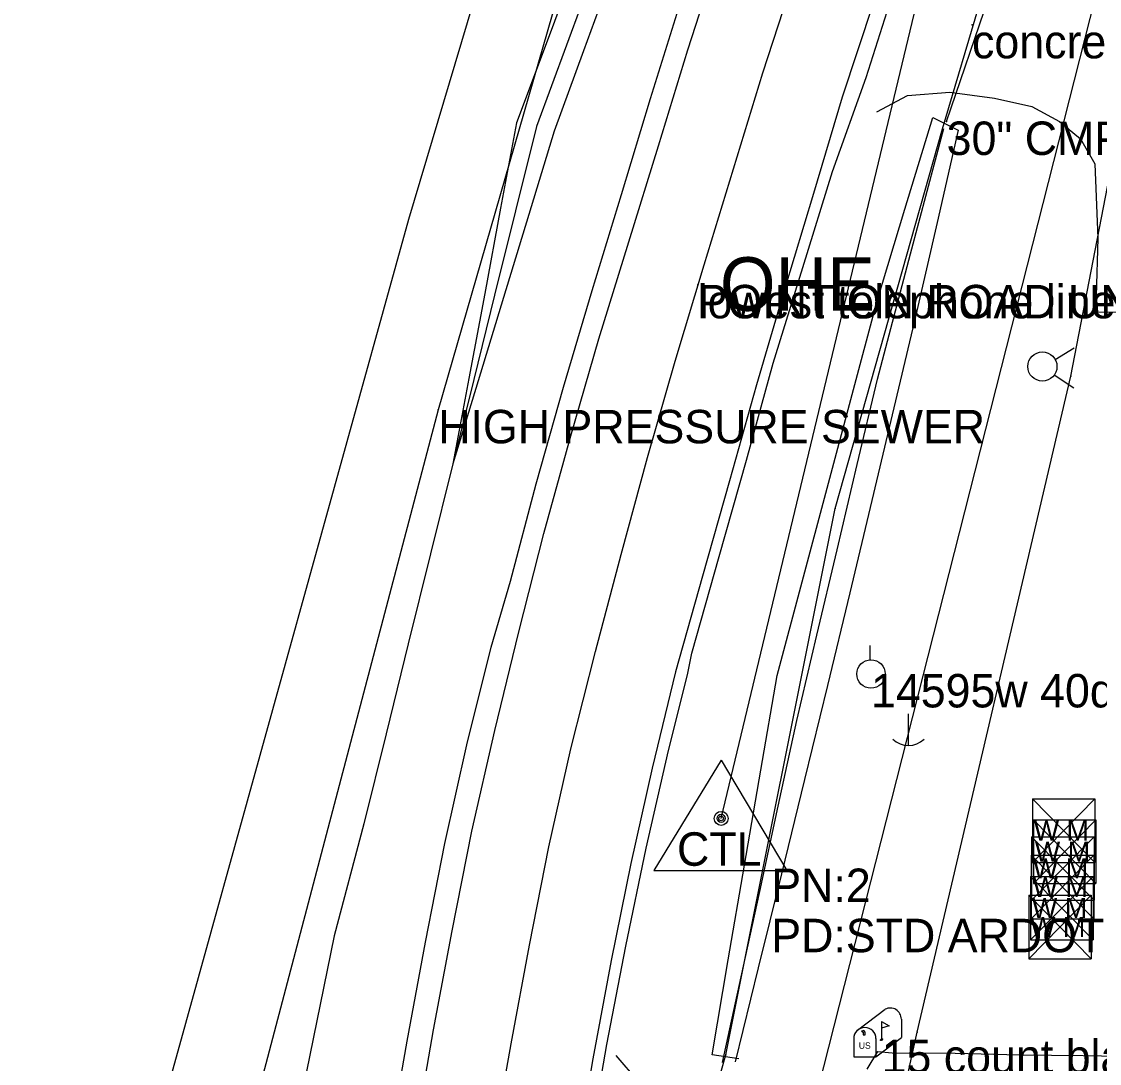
# Model space of a CAD drawing. Extents: x 1802180 to 1804859, y 572524 to 575172.
# Drawn here: x 1803144.4 to 1803305.5, y 573011.4 to 573167.1 of the extents above; entities that cross this region are included whole.
import ezdxf

# ---------------------------------------------------------------- set-up
doc = ezdxf.new("R2010")
doc.units = 0
for name, color, linetype in [('EX_EDGE_PAVEMENT', 7, 'Continuous'), ('EX_SHOULDER', 7, 'Continuous'), ('S_BASELINE', 7, 'Continuous'), ('S_DITCHLINE', 7, 'Continuous'), ('S_DRG_PT_SYM', 7, 'Continuous'), ('S_ELECTRIC_UTILITIES_ANNOT', 7, 'Continuous'), ('S_GAS_UTILITIES', 7, 'Continuous'), ('S_MAILBOX', 7, 'Continuous'), ('S_MAILBOX_ANNOT', 7, 'Continuous'), ('S_MISC_BOUNDARY', 7, 'Continuous'), ('S_MSC_PT_SYM', 7, 'Continuous'), ('S_PARKING', 7, 'Continuous'), ('S_PAVEMENT_CROWN', 7, 'Continuous'), ('S_PRIMARY_CTL', 7, 'Continuous'), ('S_PRIMARY_CTL_ANNOT', 7, 'Continuous'), ('S_SANITARY_SEWER', 7, 'Continuous'), ('S_SANITARY_SEWER_ANNOT', 7, 'Continuous'), ('S_SHOULDER', 7, 'Continuous'), ('S_SIDE_DRAIN', 7, 'Continuous'), ('S_SIDE_DRAIN_ANNOT', 7, 'Continuous'), ('S_SURVEY_TEXT', 7, 'Continuous'), ('S_SURVEY_TEXT_ANNOT', 7, 'Continuous'), ('S_UTILITY_POLE', 7, 'Continuous'), ('S_UTILITY_POLE_ANNOT', 7, 'Continuous'), ('S_UTL_PT_SYM', 7, 'Continuous'), ('S_WATER_UTILITIES', 7, 'Continuous')]:
    doc.layers.add(name, color=color, linetype=linetype)

msp = doc.modelspace()

# ---------------------------------------------------------------- linework, layer by layer
at = {"layer": 'EX_EDGE_PAVEMENT'}
for points in [[(1803203.33, 573001.42), (1803205.96, 573016.44), (1803208.73, 573031.24), (1803211.69, 573046.13), (1803215.08, 573061.15), (1803218.68, 573075.89), (1803222.45, 573090.57), (1803226.48, 573105.2), (1803230.65, 573119.7), (1803235.11, 573134.16), (1803239.56, 573148.5), (1803243.97, 573162.84), (1803248.63, 573177.34)], [(1803271.65, 573169.78), (1803267.02, 573155.77), (1803262.74, 573141.39), (1803258.4, 573127.05), (1803254.23, 573112.79), (1803250.16, 573098.45), (1803246.13, 573084.2), (1803242.13, 573069.91), (1803238.63, 573055.52), (1803235.44, 573041.29), (1803232.5, 573026.78), (1803229.77, 573012.09), (1803227.31, 572997.57)]]:
    msp.add_lwpolyline(points, dxfattribs=at)
at = {"layer": 'EX_SHOULDER'}
for points in [[(1803244.54, 573072.71), (1803248.63, 573087.13), (1803252.74, 573101.56), (1803256.68, 573116.02), (1803261.13, 573130.33), (1803265.55, 573144.67), (1803270.59, 573158.74), (1803275.14, 573173.03), (1803279.82, 573187.3), (1803284.37, 573201.59), (1803289.02, 573215.83), (1803293.78, 573230.06), (1803298.55, 573244.28), (1803303.32, 573258.5), (1803308.12, 573272.7), (1803312.96, 573286.9), (1803317.8, 573301.09), (1803322.64, 573315.29), (1803327.4, 573329.51), (1803332.12, 573343.77), (1803336.9, 573357.97)], [(1803217.45, 573083.45), (1803221.29, 573098), (1803225.36, 573112.47), (1803229.64, 573126.91), (1803234.04, 573141.25), (1803238.37, 573155.6), (1803242.85, 573169.96), (1803247.56, 573184.22), (1803252.29, 573198.46), (1803256.96, 573212.72), (1803261.68, 573226.97), (1803266.49, 573241.18), (1803271.3, 573255.39), (1803276.08, 573269.61), (1803280.88, 573283.83), (1803285.7, 573298.03), (1803290.52, 573312.24), (1803295.34, 573326.45), (1803300.24, 573340.63), (1803305.01, 573354.83)]]:
    msp.add_lwpolyline(points, dxfattribs=at)
at = {"layer": 'S_BASELINE'}
msp.add_line((1803248.92, 573048.02), (1803445.92, 573868.28), dxfattribs=at)
at = {"layer": 'S_DITCHLINE'}
for points in [[(1803289.39, 573359.67), (1803285.18, 573345.84), (1803280.96, 573332.01), (1803276.75, 573318.18), (1803272.53, 573304.35), (1803268.08, 573291.91), (1803263.63, 573279.47), (1803259.18, 573267.02), (1803254.72, 573254.58), (1803250.18, 573241.12), (1803245.65, 573227.66), (1803241.11, 573214.21), (1803236.57, 573200.75), (1803232.01, 573188.55), (1803227.46, 573176.35), (1803222.91, 573164.14), (1803218.36, 573151.94), (1803215.97, 573139.2), (1803213.59, 573126.47), (1803211.2, 573113.73), (1803208.82, 573100.99)], [(1803294.83, 573357.82), (1803290.52, 573344.09), (1803286.21, 573330.36), (1803281.9, 573316.63), (1803277.59, 573302.9), (1803273.2, 573290.32), (1803268.8, 573277.73), (1803264.41, 573265.15), (1803260.01, 573252.56), (1803255.39, 573239.11), (1803250.78, 573225.66), (1803246.16, 573212.21), (1803241.54, 573198.76), (1803237.14, 573186.74), (1803232.74, 573174.73), (1803228.35, 573162.72), (1803223.95, 573150.71), (1803220.17, 573138.28), (1803216.38, 573125.85), (1803212.6, 573113.42), (1803208.82, 573100.99)], [(1803230.29, 573175.75), (1803225.81, 573163.57), (1803221.33, 573151.39), (1803218.2, 573138.79), (1803215.07, 573126.19), (1803211.94, 573113.59), (1803208.82, 573100.99), (1803205.49, 573087.55), (1803202.16, 573074.11), (1803198.84, 573060.67), (1803195.51, 573047.23), (1803191.07, 573030.48), (1803186.39, 573007.51)], [(1803251.58, 573012.08), (1803247.57, 573012.69), (1803250, 573026.87), (1803252.44, 573041.04), (1803254.87, 573055.21), (1803257.31, 573069.39), (1803261.04, 573083.38), (1803264.77, 573097.38), (1803268.51, 573111.37), (1803272.24, 573125.36), (1803276.4, 573139.05), (1803280.56, 573152.73), (1803284.37, 573150.88), (1803281.21, 573137.04), (1803278.04, 573123.2), (1803274.74, 573109.37), (1803271.44, 573095.54), (1803268.14, 573081.71), (1803264.84, 573067.88), (1803261.39, 573053.82), (1803257.94, 573039.76), (1803254.48, 573025.7), (1803251.03, 573011.63)], [(1803249.15, 573011.56), (1803251.92, 573024.33), (1803254.69, 573037.09), (1803257.46, 573049.86), (1803260.23, 573062.63), (1803263.25, 573075.38), (1803266.26, 573088.13), (1803269.28, 573100.88), (1803272.29, 573113.64), (1803277.25, 573132.37), (1803282.21, 573151.11)]]:
    msp.add_lwpolyline(points, dxfattribs=at)
at = {"layer": 'S_DRG_PT_SYM'}
msp.add_lwpolyline([(1803282.63, 573152.15), (1803282.63, 573152.2), (1803282.63, 573152.15), (1803282.58, 573152.15), (1803282.63, 573152.15), (1803282.63, 573152.1), (1803282.63, 573152.15), (1803282.68, 573152.15)], dxfattribs=at)
at = {"layer": 'S_GAS_UTILITIES'}
for p, q in [((1803282.01, 573151.05), (1803291.88, 573184.33)), ((1803265.95, 573094.32), (1803282.01, 573151.05)), ((1803249.61, 573012.7), (1803265.95, 573094.32)), ((1803239.64, 572977.11), (1803249.61, 573012.7))]:
    msp.add_line(p, q, dxfattribs=at)
at = {"layer": 'S_MAILBOX'}
for p, q in [((1803269.29, 573016.38), (1803273.43, 573019.49)), ((1803272.91, 573017.67), (1803272.91, 573014.96)), ((1803275.86, 573018.02), (1803275.86, 573015.3)), ((1803272.06, 573012.39), (1803275.86, 573015.3)), ((1803268.74, 573015.11), (1803268.74, 573012.39)), ((1803272.06, 573015.11), (1803272.06, 573012.39)), ((1803268.74, 573012.39), (1803272.06, 573012.39))]:
    msp.add_line(p, q, dxfattribs=at)
for points in [[(1803272.91, 573017.67), (1803274.02, 573017.01), (1803272.91, 573016.66)], [(1803269.92, 573016.22), (1803270.15, 573016.09), (1803270.15, 573015.7), (1803270.45, 573015.7), (1803270.45, 573016.06), (1803270.26, 573016.31), (1803269.92, 573016.25)]]:
    msp.add_lwpolyline(points, dxfattribs=at)
for centre, end in [((1803274.2, 573018.02), 117.5718), ((1803270.4, 573015.11), 180)]:
    msp.add_arc(centre, 1.66, 0, end, dxfattribs=at)
msp.add_ellipse((1803272.91, 573014.96), major_axis=(0.145, 0.132), ratio=0.564646, dxfattribs=at)
at = {"layer": 'S_MISC_BOUNDARY'}
msp.add_lwpolyline([(1802880.88, 573735.6), (1803051.71, 573733.48), (1803213.27, 573730.83), (1803216.46, 573532.09), (1803301.63, 573530.07), (1803296.75, 573432.28), (1803274.96, 573355.36), (1803226.68, 573219.53), (1803202.19, 573137.5), (1803157.77, 572977.33), (1803158.5, 572726.69), (1802889.88, 572728.1)], dxfattribs=at)
at = {"layer": 'S_MSC_PT_SYM'}
for points in [[(1803286.42, 573166.59), (1803286.42, 573166.64), (1803286.42, 573166.59), (1803286.37, 573166.59), (1803286.42, 573166.59), (1803286.42, 573166.54), (1803286.42, 573166.59), (1803286.47, 573166.59)], [(1803245.42, 573127.74), (1803245.42, 573127.79), (1803245.42, 573127.74), (1803245.37, 573127.74), (1803245.42, 573127.74), (1803245.42, 573127.69), (1803245.42, 573127.74), (1803245.47, 573127.74)]]:
    msp.add_lwpolyline(points, dxfattribs=at)
at = {"layer": 'S_PARKING'}
for points in [[(1803272.22, 573153.62), (1803276.76, 573156.03), (1803283.12, 573156.53), (1803289.76, 573155.63), (1803295.36, 573154.41), (1803299.49, 573152.13), (1803302.62, 573149.58), (1803304.78, 573145.84), (1803305.21, 573134.7), (1803304.96, 573126.07), (1803305.2, 573123.69), (1803309.92, 573123.68), (1803319.81, 573123.41), (1803331.78, 573123.25), (1803335.8, 573123.23), (1803335.81, 573122.76), (1803335.65, 573117.44), (1803339.14, 573117.28)], [(1803272.22, 573153.62), (1803276.76, 573156.03), (1803283.12, 573156.53), (1803289.76, 573155.63), (1803295.36, 573154.41), (1803299.49, 573152.13), (1803302.62, 573149.58), (1803304.78, 573145.84), (1803305.21, 573134.7), (1803304.96, 573126.07), (1803305.2, 573123.69), (1803309.92, 573123.68)], [(1803233.2, 573012.6), (1803236.54, 573008.71)], [(1803233.2, 573012.6), (1803236.54, 573008.71)], [(1803270.73, 573010.53), (1803272.33, 573013.18), (1803274.47, 573013.01), (1803283.9, 573012.93), (1803293.57, 573012.71), (1803303.01, 573012.57), (1803308.51, 573012.47), (1803323.55, 573012.32), (1803327.49, 573012.2), (1803342.61, 573012.05), (1803352.87, 573011.83), (1803367.72, 573011.79), (1803375.31, 573011.48), (1803390.31, 573011.23)], [(1803270.73, 573010.53), (1803272.33, 573013.18), (1803274.47, 573013.01), (1803283.9, 573012.93), (1803293.57, 573012.71), (1803303.01, 573012.57), (1803308.51, 573012.47), (1803323.55, 573012.32), (1803327.49, 573012.2), (1803342.61, 573012.05), (1803352.87, 573011.83), (1803367.72, 573011.79), (1803375.31, 573011.48), (1803390.31, 573011.23)]]:
    msp.add_lwpolyline(points, dxfattribs=at)
at = {"layer": 'S_PAVEMENT_CROWN'}
msp.add_lwpolyline([(1803214.89, 572999.56), (1803217.53, 573014.33), (1803220.29, 573029.07), (1803223.17, 573043.79), (1803226.47, 573058.42), (1803230.13, 573072.97), (1803233.98, 573087.47), (1803237.94, 573101.93), (1803242.08, 573116.35), (1803246.37, 573130.72), (1803250.76, 573145.07), (1803255.16, 573159.41), (1803259.77, 573173.68)], dxfattribs=at)
at = {"layer": 'S_PRIMARY_CTL'}
for p, q in [((1803248.92, 573056.72), (1803238.89, 573040.21)), ((1803248.92, 573056.72), (1803258.74, 573040.21)), ((1803238.89, 573040.21), (1803258.74, 573040.21))]:
    msp.add_line(p, q, dxfattribs=at)
for radius in [1.04, 0.609, 0.344]:
    msp.add_circle((1803248.92, 573048.02), radius, dxfattribs=at)
at = {"layer": 'S_SANITARY_SEWER'}
for p, q in [((1803235.59, 573209.54), (1803206.64, 573109.06)), ((1803253.84, 572969.86), (1803305.33, 573172.39)), ((1803206.64, 573109.06), (1803178.99, 573004.24))]:
    msp.add_line(p, q, dxfattribs=at)
at = {"layer": 'S_SHOULDER'}
for points in [[(1803188.06, 572774.94), (1803187.64, 572789.93), (1803187.25, 572804.96), (1803187.05, 572819.98), (1803186.96, 572835.01), (1803187.13, 572850.03), (1803187.6, 572865.07), (1803188.05, 572880.08), (1803188.63, 572895.09), (1803189.46, 572910.14), (1803190.47, 572925.15), (1803191.68, 572940.15), (1803193.18, 572955.14), (1803195.08, 572970.09), (1803197.21, 572985), (1803199.42, 572999.92), (1803202, 573014.73), (1803204.73, 573029.52), (1803207.64, 573044.28), (1803210.93, 573059.01), (1803214.56, 573073.63), (1803217.45, 573083.45)], [(1803217.19, 572775.54), (1803216.95, 572790.56), (1803216.67, 572805.5), (1803216.65, 572820.48), (1803216.72, 572835.48), (1803217.08, 572850.44), (1803217.44, 572865.41), (1803217.82, 572880.43), (1803218.13, 572895.35), (1803219.14, 572910.28), (1803220.26, 572925.21), (1803221.76, 572940.08), (1803223.21, 572954.99), (1803224.98, 572969.82), (1803227.01, 572984.65), (1803229.31, 572999.47), (1803231.85, 573014.23), (1803234.7, 573028.93), (1803237.73, 573043.58), (1803241.04, 573058.18), (1803243.89, 573069.48), (1803244.54, 573072.71)]]:
    msp.add_lwpolyline(points, dxfattribs=at)
at = {"layer": 'S_SIDE_DRAIN'}
msp.add_line((1803282.63, 573152.15), (1803292.48, 573181.22), dxfattribs=at)
at = {"layer": 'S_SURVEY_TEXT'}
msp.add_line((1803248.74, 573123.87), (1803248.74, 573123.87), dxfattribs=at)
at = {"layer": 'S_UTILITY_POLE'}
for p, q in [((1803271.2, 573071.74), (1803271.2, 573073.85)), ((1803276.86, 573063.63), (1803276.86, 573058.9))]:
    msp.add_line(p, q, dxfattribs=at)
msp.add_circle((1803271.32, 573069.6), 2.13, dxfattribs=at)
msp.add_arc((1803276.92, 573062.33), 3.41, 226.3972, 313.6028, dxfattribs=at)
at = {"layer": 'S_UTL_PT_SYM'}
for points in [[(1803282.01, 573151.05), (1803282.01, 573151.1), (1803282.01, 573151.05), (1803281.96, 573151.05), (1803282.01, 573151.05), (1803282.01, 573151), (1803282.01, 573151.05), (1803282.06, 573151.05)], [(1803245.42, 573127.74), (1803245.42, 573127.79), (1803245.42, 573127.74), (1803245.37, 573127.74), (1803245.42, 573127.74), (1803245.42, 573127.69), (1803245.42, 573127.74), (1803245.47, 573127.74)], [(1803301.21, 573114.11), (1803301.21, 573114.16), (1803301.21, 573114.11), (1803301.16, 573114.11), (1803301.21, 573114.11), (1803301.21, 573114.06), (1803301.21, 573114.11), (1803301.26, 573114.11)], [(1803206.64, 573109.06), (1803206.64, 573109.11), (1803206.64, 573109.06), (1803206.59, 573109.06), (1803206.64, 573109.06), (1803206.64, 573109.01), (1803206.64, 573109.06), (1803206.69, 573109.06)], [(1803265.95, 573094.32), (1803265.95, 573094.37), (1803265.95, 573094.32), (1803265.9, 573094.32), (1803265.95, 573094.32), (1803265.95, 573094.27), (1803265.95, 573094.32), (1803266, 573094.32)], [(1803278.2, 573016.08), (1803278.2, 573016.13), (1803278.2, 573016.08), (1803278.15, 573016.08), (1803278.2, 573016.08), (1803278.2, 573016.03), (1803278.2, 573016.08), (1803278.25, 573016.08)], [(1803249.61, 573012.7), (1803249.61, 573012.75), (1803249.61, 573012.7), (1803249.56, 573012.7), (1803249.61, 573012.7), (1803249.61, 573012.65), (1803249.61, 573012.7), (1803249.66, 573012.7)]]:
    msp.add_lwpolyline(points, dxfattribs=at)
at = {"layer": 'S_WATER_UTILITIES'}
for p, q in [((1803301.21, 573114.11), (1803313.18, 573176.27)), ((1803298.85, 573116.6), (1803301.67, 573118.33)), ((1803278.2, 573016.08), (1803301.21, 573114.11)), ((1803298.72, 573114.29), (1803301.63, 573112.36)), ((1803295.45, 573050.93), (1803304.79, 573050.93)), ((1803295.45, 573050.93), (1803295.45, 573041.44)), ((1803295.45, 573050.93), (1803304.79, 573041.44)), ((1803304.79, 573050.93), (1803295.45, 573041.44)), ((1803304.79, 573050.93), (1803304.79, 573041.44)), ((1803295.61, 573047.79), (1803304.95, 573047.79)), ((1803295.61, 573047.79), (1803295.61, 573038.29)), ((1803295.61, 573047.79), (1803304.95, 573038.29)), ((1803304.95, 573047.79), (1803295.61, 573038.29)), ((1803304.95, 573047.79), (1803304.95, 573038.29)), ((1803295.32, 573045.28), (1803304.66, 573045.28)), ((1803295.32, 573045.28), (1803295.32, 573035.78)), ((1803295.32, 573045.28), (1803304.66, 573035.78)), ((1803304.66, 573045.28), (1803295.32, 573035.78)), ((1803304.66, 573045.28), (1803304.66, 573035.78)), ((1803295.27, 573042.51), (1803304.61, 573042.51)), ((1803295.27, 573042.51), (1803295.27, 573033.02)), ((1803295.27, 573042.51), (1803304.61, 573033.02)), ((1803304.61, 573042.51), (1803295.27, 573033.02)), ((1803295.45, 573041.44), (1803304.79, 573041.44)), ((1803304.61, 573042.51), (1803304.61, 573033.02)), ((1803295.17, 573039.36), (1803304.51, 573039.36)), ((1803295.17, 573039.36), (1803295.17, 573029.86)), ((1803295.17, 573039.36), (1803304.51, 573029.86)), ((1803304.51, 573039.36), (1803295.17, 573029.86)), ((1803295.61, 573038.29), (1803304.95, 573038.29)), ((1803304.51, 573039.36), (1803304.51, 573029.86)), ((1803294.9, 573036.53), (1803304.24, 573036.53)), ((1803294.9, 573036.53), (1803294.9, 573027.04)), ((1803294.9, 573036.53), (1803304.24, 573027.04)), ((1803304.24, 573036.53), (1803294.9, 573027.04)), ((1803304.24, 573036.53), (1803304.24, 573027.04)), ((1803295.32, 573035.78), (1803304.66, 573035.78)), ((1803295.27, 573033.02), (1803304.61, 573033.02)), ((1803295.17, 573029.86), (1803304.51, 573029.86)), ((1803294.9, 573027.04), (1803304.24, 573027.04)), ((1803262.53, 572945.13), (1803278.2, 573016.08))]:
    msp.add_line(p, q, dxfattribs=at)
msp.add_circle((1803296.94, 573115.54), 2.18, dxfattribs=at)

# ---------------------------------------------------------------- texts
at = {"layer": 'S_ELECTRIC_UTILITIES_ANNOT'}
msp.add_text('lowest telephone line ', height=5, dxfattribs=at).set_placement((1803245.42, 573122.74))
at = {"layer": 'S_MAILBOX'}
msp.add_text('US', height=0.96, rotation=360, dxfattribs=at).set_placement((1803269.5, 573013.59))
at = {"layer": 'S_MAILBOX_ANNOT'}
msp.add_text('15 count black metal mb for apt', height=5, dxfattribs=at).set_placement((1803272.91, 573009.96))
at = {"layer": 'S_PRIMARY_CTL'}
msp.add_text('CTL', height=5, rotation=360, dxfattribs=at).set_placement((1803242.33, 573040.94))
at = {"layer": 'S_PRIMARY_CTL_ANNOT'}
for s, p in [('PN:2', (1803256.42, 573035.52)), ('PD:STD ARDOT MON. STAMPED PN:2 18', (1803256.42, 573028.02))]:
    msp.add_text(s, height=5, dxfattribs=at).set_placement(p)
at = {"layer": 'S_SANITARY_SEWER_ANNOT'}
msp.add_text('HIGH PRESSURE SEWER  ', height=5, dxfattribs=at).set_placement((1803206.64, 573104.06))
at = {"layer": 'S_SIDE_DRAIN_ANNOT'}
msp.add_text('30" CMP', height=5, dxfattribs=at).set_placement((1803282.63, 573147.15))
at = {"layer": 'S_SURVEY_TEXT_ANNOT'}
for s, height, p in [('concrete dw', 5, (1803286.42, 573161.59)), ('OHE', 8, (1803248.74, 573123.87)), ('POINT ON ROAD UNDER LOWEST LINE ', 5, (1803245.42, 573122.74))]:
    msp.add_text(s, height=height, dxfattribs=at).set_placement(p)
at = {"layer": 'S_UTILITY_POLE_ANNOT'}
msp.add_text('14595w 40qr', height=5, dxfattribs=at).set_placement((1803271.32, 573064.6))
at = {"layer": 'S_WATER_UTILITIES'}
for p in [(1803295.65, 573044.7), (1803295.82, 573041.55), (1803295.52, 573039.04), (1803295.48, 573036.28), (1803295.38, 573033.12), (1803295.11, 573030.3)]:
    msp.add_text('W M', height=3, rotation=360, dxfattribs=at).set_placement(p)

doc.saveas('drawing.dxf')
